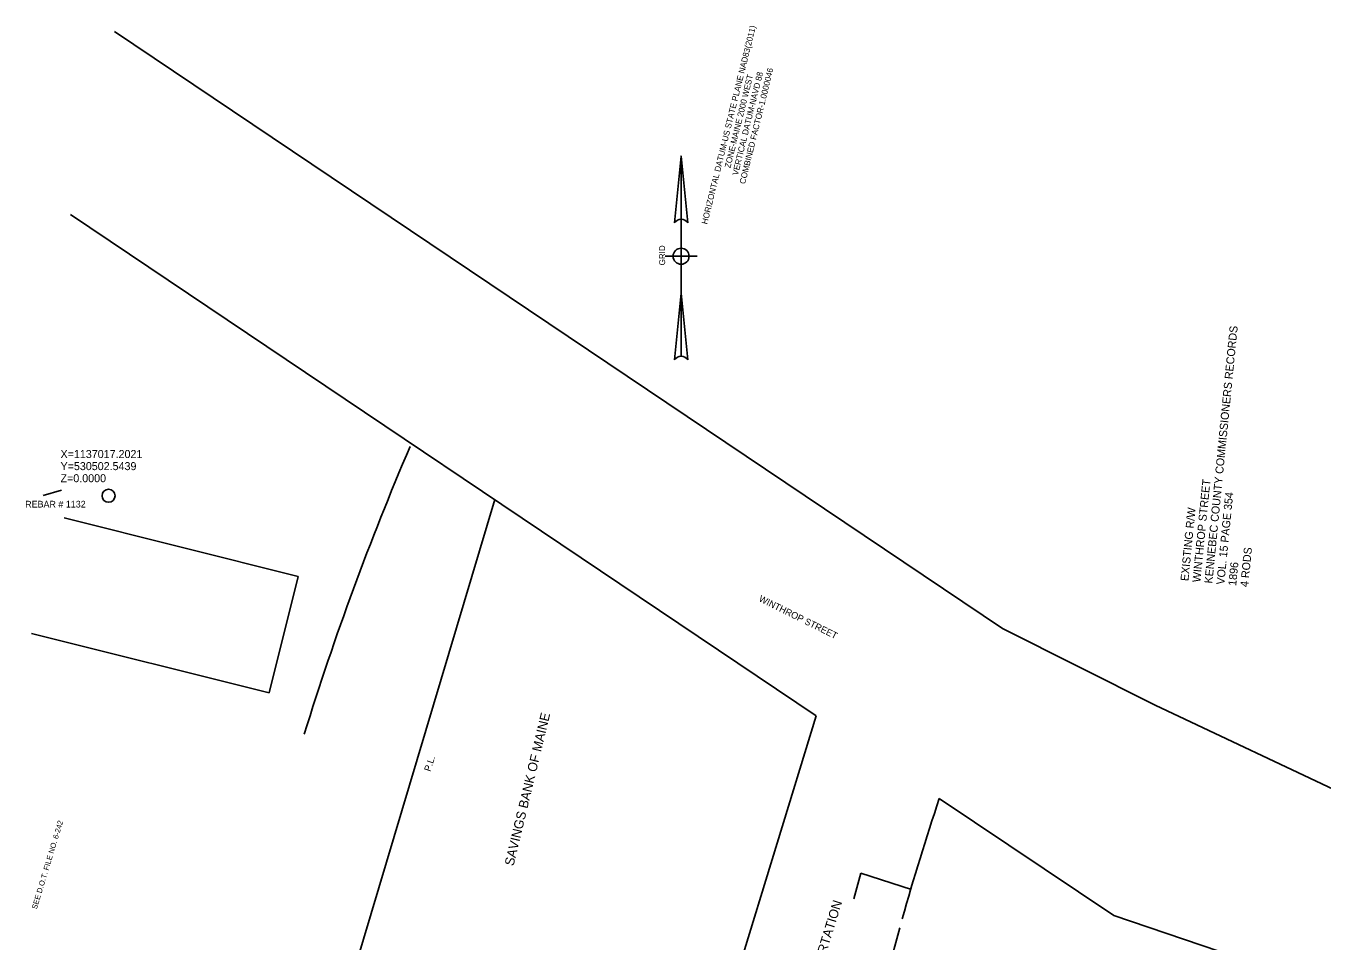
# Model space of a CAD drawing. Extents: x 1133267 to 1139526, y 528613 to 531538.
# Drawn here: x 1136720.7 to 1137206.5, y 530418.5 to 530761.3 of the extents above; entities that cross this region are included whole.
import ezdxf

# ---------------------------------------------------------------- set-up
doc = ezdxf.new("R2010")
doc.units = 0
for name, color, linetype in [('E_Property_Line', 7, 'Continuous'), ('E_ROW_Line', 7, 'Continuous'), ('E_ROW_Railroad', 7, 'Continuous'), ('E_ROW_TieLine', 7, 'Continuous'), ('EX ROW JUNK', 7, 'Continuous'), ('MISCELLN TEXT', 7, 'Continuous'), ('North Arrows', 7, 'Continuous'), ('PRP OWNER NAMES', 7, 'Continuous'), ('ROW REFERENCES', 7, 'Continuous')]:
    doc.layers.add(name, color=color, linetype=linetype)

msp = doc.modelspace()

# ---------------------------------------------------------------- linework, layer by layer
at = {"layer": 'E_Property_Line'}
msp.add_lwpolyline([(1136896.45, 530583.84), (1136841.53, 530399.91), (1136848.68, 530397.83), (1136845.43, 530386.27), (1136941.45, 530358.33), (1136944.69, 530369.88), (1136973.5, 530361.5)], dxfattribs=at)
at = {"layer": 'E_ROW_Line'}
for p, q in [((1137086.7, 530535.53), (1136753.88, 530759.16)), ((1137143.94, 530506.79), (1137086.7, 530535.53)), ((1137219.07, 530471.34), (1137143.94, 530506.79))]:
    msp.add_line(p, q, dxfattribs=at)
for points in [[(1137016.94, 530502.89), (1136737.43, 530690.7)], [(1137199.91, 530404.29), (1137194.29, 530405.65), (1137128.41, 530427.99), (1137063.03, 530471.92)]]:
    msp.add_lwpolyline(points, dxfattribs=at)
at = {"layer": 'E_ROW_Railroad'}
for p, q in [((1136973.5, 530361.5), (1137016.94, 530502.89)), ((1136970.63, 530140.51), (1137048.18, 530423.41))]:
    msp.add_line(p, q, dxfattribs=at)
msp.add_arc((1138106.62, 530125.13), 1099.7, 161.61845, 164.07652, dxfattribs=at)
at = {"layer": 'E_ROW_TieLine'}
for p, q in [((1136727.21, 530585.43), (1136734.06, 530587.4)), ((1136735.05, 530576.99), (1136822.76, 530555.08)), ((1136822.76, 530555.08), (1136811.85, 530511.42)), ((1136811.85, 530511.42), (1136722.9, 530533.64))]:
    msp.add_line(p, q, dxfattribs=at)
msp.add_circle((1136751.71, 530585.3), 2.44, dxfattribs=at)
at = {"layer": 'EX ROW JUNK'}
for q in [(1137030.96, 530434.29), (1137052.6, 530437.73)]:
    msp.add_line((1137033.59, 530443.94), q, dxfattribs=at)
msp.add_arc((1137875.51, 530170.59), 1099.7, 156.80177, 162.78583, dxfattribs=at)
at = {"layer": 'North Arrows'}
for p, q in [((1136963.78, 530687.52), (1136966.28, 530712.52)), ((1136966.28, 530712.52), (1136966.28, 530637.52)), ((1136966.28, 530712.52), (1136968.78, 530687.52)), ((1136960.28, 530675.02), (1136972.28, 530675.02)), ((1136963.78, 530636.18), (1136966.28, 530661.18)), ((1136966.28, 530661.18), (1136968.78, 530636.18))]:
    msp.add_line(p, q, dxfattribs=at)
for points in [[(1136966.28, 530688.86), (1136966.28, 530712.52), (1136963.78, 530687.52)], [(1136968.78, 530687.52), (1136966.28, 530712.52), (1136966.28, 530688.86)], [(1136966.28, 530678.02), (1136966.28, 530675.02), (1136969.28, 530675.02)], [(1136966.28, 530672.02), (1136966.28, 530675.02), (1136963.28, 530675.02)], [(1136966.28, 530637.52), (1136966.28, 530661.18), (1136963.78, 530636.18)], [(1136968.78, 530636.18), (1136966.28, 530661.18), (1136966.28, 530637.52)]]:
    msp.add_lwpolyline(points, dxfattribs=at)
msp.add_circle((1136966.28, 530675.02), 3, dxfattribs=at)
for centre, start, end in [((1136966.28, 530685.86), 33.5573, 146.4427), ((1136966.28, 530685.86), 90, 146.4427), ((1136966.28, 530685.86), 33.5573, 90), ((1136966.28, 530675.02), 0, 90), ((1136966.28, 530675.02), 180, 270), ((1136966.28, 530634.52), 33.5573, 146.4427), ((1136966.28, 530634.52), 90, 146.4427), ((1136966.28, 530634.52), 33.5573, 90)]:
    msp.add_arc(centre, 3, start, end, dxfattribs=at)

# ---------------------------------------------------------------- texts
at = {"layer": 'E_Property_Line'}
msp.add_text('P.L.', height=2.5, rotation=71.1238, dxfattribs=at).set_placement((1136872.25, 530481.79))
at = {"layer": 'MISCELLN TEXT'}
for s, height, p in [('X=1137017.2021', 3, (1136733.71, 530599.42)), ('Y=530502.5439', 3, (1136733.71, 530594.89)), ('Z=0.0000', 3, (1136733.71, 530590.36)), ('REBAR # 1132', 2.5, (1136720.47, 530580.89))]:
    msp.add_text(s, height=height, dxfattribs=at).set_placement(p)
msp.add_text('WINTHROP STREET', height=2.5, rotation=333.5467, dxfattribs=at).set_placement((1136995.14, 530545.9))
at = {"layer": 'North Arrows'}
for s, height, rotation, p in [('HORIZONTAL DATUM-US STATE PLANE NAD83(2011)', 2.2488, 76.2277, (1136976.07, 530686.83)), ('ZONE-MAINE 2000 WEST', 2.2488, 76.2277, (1136984.73, 530707.9)), ('VERTICAL DATUM-NAVD 88', 2.2488, 76.2277, (1136987.55, 530705.15)), ('COMBINED FACTOR-1.0000046', 2.2488, 76.2277, (1136990.25, 530701.9)), ('GRID', 2.249, 90, (1136960.28, 530671.59))]:
    msp.add_text(s, height=height, rotation=rotation, dxfattribs=at).set_placement(p)
at = {"layer": 'PRP OWNER NAMES'}
for s, rotation, p in [('SAVINGS BANK OF MAINE', 76.4513, (1136903.47, 530446.42)), ('DEPARTMENT OF TRANSPORTATION', 72.8069, (1137001.68, 530352.4))]:
    msp.add_text(s, height=3.5, rotation=rotation, dxfattribs=at).set_placement(p)
at = {"layer": 'ROW REFERENCES'}
for s, height, rotation, p in [('KENNEBEC COUNTY COMMISSIONERS RECORDS', 3, 84.3485, (1137165.32, 530552.32)), ('WINTHROP STREET', 3, 84.3485, (1137160.84, 530552.76)), ('VOL. 15 PAGE 354', 3, 84.3485, (1137169.79, 530551.88)), ('EXISTING R/W', 3, 84.3485, (1137156.36, 530553.21)), ('4 RODS', 3, 84.3485, (1137178.75, 530550.99)), ('1896', 3, 84.3485, (1137174.27, 530551.43)), ('SEE D.O.T. FILE NO. 6-242', 2, 73.258, (1136724.79, 530430.22))]:
    msp.add_text(s, height=height, rotation=rotation, dxfattribs=at).set_placement(p)

doc.saveas('drawing.dxf')
